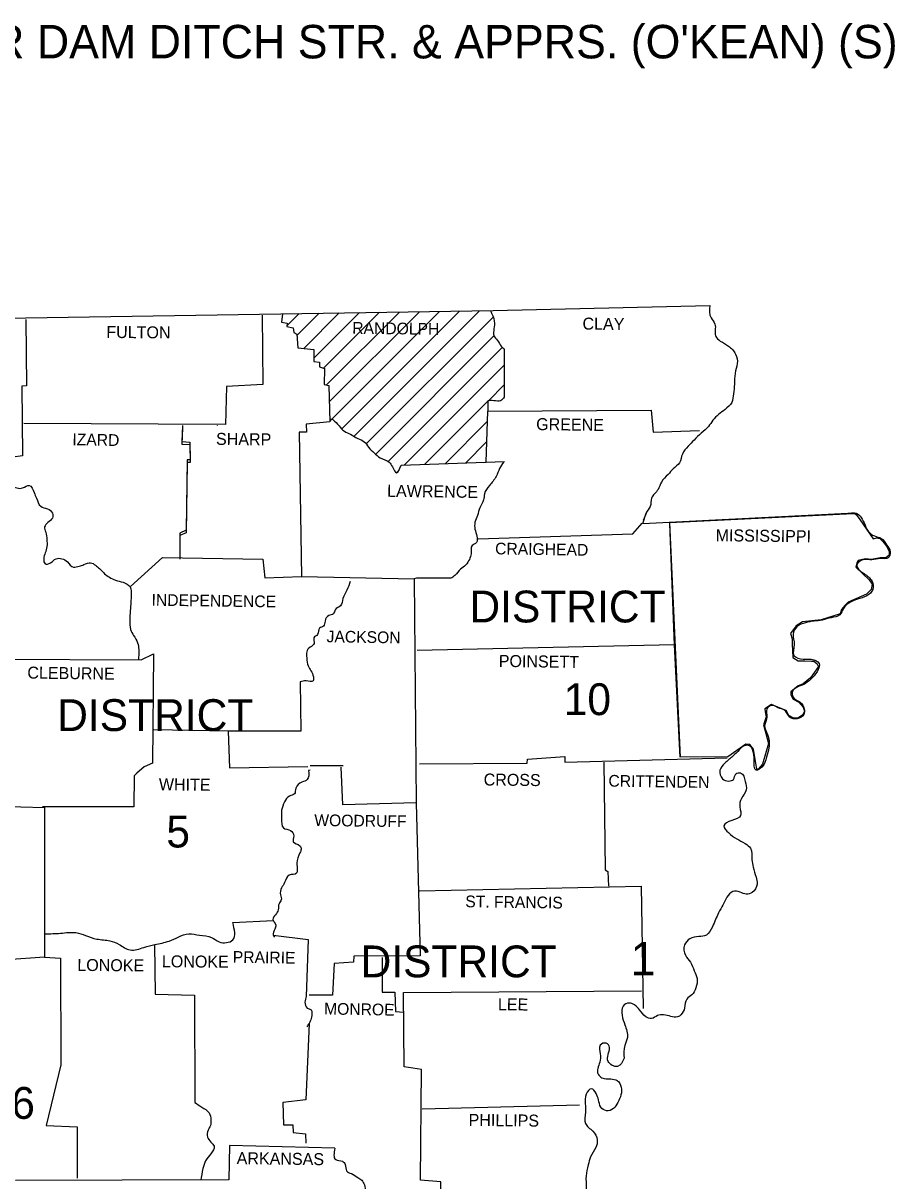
# Model space of a CAD drawing. Extents: x 166 to 3406, y 71 to 2074.
# Drawn here: x 2979.2 to 3284.8, y 1629.3 to 2035 of the extents above; entities that cross this region are included whole.
import ezdxf

# ---------------------------------------------------------------- set-up
doc = ezdxf.new("R2010")
doc.units = 0
for name, color, linetype in [('1', 7, 'Continuous'), ('2', 7, 'Continuous'), ('3', 7, 'Continuous'), ('R_Border', 7, 'Continuous'), ('S_MISC_BOUNDARY', 7, 'Continuous')]:
    doc.layers.add(name, color=color, linetype=linetype)

msp = doc.modelspace()

# ---------------------------------------------------------------- linework, layer by layer
at = {"layer": '1'}
for p, q in [((3071.63, 1928.88), (3075.94, 1933.18)), ((3075.16, 1925.49), (3082.96, 1933.29)), ((3077.59, 1921), (3089.99, 1933.4)), ((3081.01, 1917.5), (3097.02, 1933.51)), ((3084.5, 1914.07), (3104.05, 1933.62)), ((3085.51, 1908.16), (3111.08, 1933.73)), ((3086.47, 1902.21), (3118.1, 1933.84)), ((3086.67, 1895.49), (3125.13, 1933.95)), ((3090.89, 1892.79), (3132.16, 1934.06)), ((3095.19, 1890.17), (3139.19, 1934.17)), ((3099.42, 1887.48), (3144.12, 1932.19)), ((3102.75, 1883.89), (3144.23, 1925.37)), ((3107.2, 1881.43), (3147.11, 1921.33)), ((3112.76, 1880.07), (3147.77, 1915.08)), ((3142.25, 1902.63), (3147.81, 1908.2)), ((3119.91, 1880.3), (3142.06, 1902.45)), ((3127.07, 1880.54), (3141.96, 1895.43)), ((3134.22, 1880.77), (3141.75, 1888.31)), ((3141.37, 1881), (3141.55, 1881.18)), ((3110.08, 1877.38), (3111.01, 1878.32)), ((3196.36, 1859.58), (3197.54, 1863.21)), ((3196.66, 1860.76), (3197.83, 1863.6)), ((3079.74, 1774.85), (3091.38, 1774.85))]:
    msp.add_line(p, q, dxfattribs=at)
for points in [[(2683.09, 1931.5), (2841.3, 1931.4), (2980.13, 1931.69), (3143.92, 1934.24), (3219.84, 1936)], [(2980.13, 1931.11), (2980.33, 1907.82), (2978.67, 1907.72), (2978.96, 1883.36), (2972.11, 1882.38), (2972.7, 1875.83), (2975.05, 1872.79), (2974.85, 1865.06), (2961.54, 1864.57), (2961.06, 1852.64), (2948.92, 1852.25), (2948.34, 1837.77), (2949.02, 1836.59), (2949.31, 1813.5), (2970.25, 1812.13), (2969.96, 1760.57), (2986.59, 1760.08), (2986.59, 1707.64), (2973.48, 1706.66), (2972.5, 1695.11), (2950.49, 1695.02)], [(3063.01, 1932.57), (3063.2, 1908.31), (3050.48, 1907.62), (3050.09, 1894.32), (2979.35, 1894.71)], [(3070.13, 1933.09), (3069.76, 1930.13), (3071.71, 1929.83), (3071.62, 1928.66), (3073.87, 1928.17), (3074.06, 1926.61), (3075.14, 1925.92), (3075.43, 1921.22), (3081.01, 1920.64), (3081.01, 1916.43), (3083.06, 1916.14), (3083.06, 1914.47), (3084.82, 1913.98), (3084.73, 1908.31), (3086.29, 1908.02), (3086.68, 1895.2), (3078.37, 1894.42), (3078.46, 1891.68), (3075.92, 1891.58), (3076.8, 1841.09), (3116.23, 1840.21), (3116.92, 1761.74), (3091.18, 1761.06), (3090.69, 1774.27)], [(3147.74, 1920.83), (3147.83, 1903.91)], [(3141.54, 1881.08), (3142.06, 1899.01), (3142.06, 1899.01), (3199.3, 1899.31), (3200.08, 1891.68), (3216.22, 1892.26)], [(3035.02, 1894.02), (3034.83, 1888.35), (3037.57, 1888.15), (3037.66, 1881.89), (3036.69, 1881.89), (3036.29, 1857.24), (3034.04, 1856.26), (3034.04, 1848.04)], [(3035.02, 1893.14), (3034.83, 1887.47), (3037.57, 1887.27), (3037.66, 1881.01), (3036.69, 1881.01), (3036.29, 1856.36), (3034.04, 1855.38), (3034.04, 1847.16)], [(3047.25, 1893.83), (3047.35, 1893.93)], [(3111.63, 1880.03), (3147.93, 1881.31)], [(3196.36, 1859.58), (3270.62, 1863.4)], [(3138.64, 1854.2), (3192.94, 1855.96), (3196.17, 1859.68)], [(3205.75, 1859.49), (3207.42, 1817.12), (3209.37, 1777.69)], [(3016.82, 1837.57), (3027.98, 1847.65), (3063.2, 1847.16), (3063.89, 1840.6), (3076.7, 1841.09)], [(3129.05, 1840.41), (3117.11, 1840.41), (3116.23, 1840.21)], [(2970.25, 1812.13), (3020.54, 1811.84), (3024.85, 1813.89), (3024.55, 1775.64), (3021.62, 1774.37), (3018.98, 1772.12), (3018.1, 1771.23), (3018, 1760.28), (2986, 1760.28)], [(3207.42, 1817.12), (3117.31, 1815.07)], [(3076.31, 1804.11), (3076.51, 1786.89), (3051.07, 1786.79), (3024.95, 1787.28)], [(3051.07, 1786.79), (3051.46, 1773.97), (3078.95, 1774.46)], [(3118.09, 1775.44), (3155.86, 1775.64), (3155.95, 1777.01), (3169.06, 1777.99), (3169.06, 1775.93), (3226.01, 1777.5)], [(3079.74, 1773.19), (3079.25, 1773.09)], [(3182.76, 1775.93), (3183.25, 1738.26), (3184.13, 1737.68), (3184.43, 1732.59)], [(3116.92, 1761.74), (3118.38, 1708.13), (3095.1, 1708.03), (3095, 1705.88), (3088.25, 1705.49), (3087.66, 1694.33), (3079.44, 1694.33)], [(3118.09, 1730.92), (3195.78, 1732.49)], [(3195.78, 1732.49), (3196.56, 1689.64)], [(3052.63, 1719.77), (3066.82, 1720.46)], [(3025.24, 1712.14), (3025.43, 1694.63), (3039.23, 1694.33), (3039.33, 1656.76)], [(3066.82, 1715.37), (3079.05, 1713.8), (3078.37, 1693.84)], [(2986.59, 1707.64), (2992.27, 1707.25), (2992.36, 1669.87), (2987.28, 1648.64), (2998.14, 1648.15), (2998.04, 1630.15)], [(3105.08, 1707.54), (3104.98, 1695.41), (3109.48, 1695.41), (3109.68, 1688.66), (3112.51, 1688.36)], [(3118.09, 1608.62), (3125.72, 1609.11), (3125.62, 1628.97), (3118.48, 1629.46), (3118.87, 1668.31), (3112.71, 1669.19), (3112.51, 1695.31), (3195.97, 1695.9)], [(3079.44, 1684.45), (3078.27, 1657.64), (3070.25, 1656.76), (3070.44, 1648.84), (3073.67, 1648.93), (3073.77, 1646.19), (3078.17, 1645.71), (3078.27, 1642.48)], [(3119.07, 1654.51), (3174.25, 1655.88)], [(3088.44, 1640.72), (3051.46, 1641.69), (3051.26, 1629.66), (2976.42, 1629.37)]]:
    msp.add_lwpolyline(points, dxfattribs=at)
for points in [[(3219.84, 1936), (3220.33, 1931.69), (3221.7, 1929.44), (3221.9, 1925.33), (3223.56, 1923.57), (3226.4, 1921.81), (3228.94, 1918.97), (3229.53, 1915.65), (3228.75, 1912.22), (3228.55, 1908.41), (3228.16, 1905.08), (3227.57, 1902.05), (3225.23, 1899.6), (3222.97, 1897.84), (3220.92, 1895.79), (3219.45, 1893.63), (3216.91, 1891.29), (3214.36, 1888.84), (3212.31, 1886.69), (3210.26, 1883.95), (3209.28, 1880.91), (3207.03, 1878.76), (3205.27, 1876.8), (3202.92, 1874.16), (3201.74, 1871.52), (3199.49, 1868.49), (3199, 1865.55), (3197.54, 1863.21), (3197.44, 1862.81)], [(3142.98, 1934.23), (3144.31, 1930.52), (3144.21, 1927.88), (3144.21, 1925.43), (3145.48, 1923.77), (3146.76, 1921.71), (3147.74, 1920.83)], [(3147.83, 1903.91), (3146.56, 1902.63), (3144.12, 1902.63), (3142.06, 1902.63)], [(3087.76, 1896.08), (3089.91, 1893.83), (3091.77, 1891.97), (3093.92, 1890.89), (3096.47, 1889.43), (3098.72, 1888.25), (3100.18, 1886.39), (3102.24, 1884.34), (3104.29, 1882.68), (3107.52, 1881.11), (3108.6, 1879.45), (3110.07, 1877.39), (3111.63, 1880.03)], [(3147.64, 1881.21), (3146.17, 1878.86), (3145, 1876.12), (3142.65, 1872.99), (3140.89, 1869.96), (3140.59, 1867.9), (3139.22, 1865.16), (3138.44, 1862.42), (3137.56, 1860.07), (3137.56, 1857.63), (3138.24, 1855.18), (3138.05, 1852.93), (3136.58, 1851.86), (3136.19, 1849.02), (3135.6, 1847.06), (3134.33, 1845.1), (3132.47, 1843.64), (3130.52, 1841.39), (3129.05, 1840.41)], [(2975.05, 1872.79), (2978.96, 1872.11), (2981.31, 1872.99), (2982.97, 1870.45), (2983.85, 1868.49), (2985.32, 1865.65), (2987.67, 1864.77), (2989.43, 1863.21), (2989.43, 1861.54), (2987.86, 1859.98), (2986.69, 1858.41), (2987.08, 1856.55), (2987.47, 1854.01), (2987.47, 1851.56), (2986.89, 1849.31), (2986.4, 1847.26), (2986.89, 1845.5), (2988.74, 1845.79), (2990.7, 1847.26), (2992.76, 1847.26), (2994.71, 1846.18), (2996.77, 1844.32), (2998.82, 1844.71), (3000.49, 1845.2), (3002.83, 1845.89), (3004.5, 1845.01), (3005.96, 1843.83), (3007.73, 1841.97), (3009.39, 1840.8), (3011.54, 1839.72), (3014.18, 1839.04), (3016.63, 1837.38), (3017.02, 1834.54), (3016.92, 1832.09), (3016.73, 1829.06), (3016.53, 1825.73), (3016.82, 1822.5), (3017.9, 1820.35), (3019.27, 1817.81), (3019.66, 1815.46), (3019.56, 1811.74)], [(3269.55, 1863.3), (3270.62, 1863.4), (3273.95, 1859.88), (3275.42, 1856.94), (3277.57, 1855.28), (3280.02, 1854.4), (3281.87, 1852.15), (3283.15, 1849.7), (3282.46, 1847.55), (3279.72, 1847.35), (3276.69, 1846.87), (3273.75, 1846.96), (3271.41, 1845.01), (3273.56, 1842.36), (3276.4, 1839.92), (3277.18, 1837.28), (3275.61, 1834.73), (3272.48, 1833.36), (3269.45, 1832.19), (3266.71, 1829.84), (3265.44, 1827.59), (3262.4, 1826.61), (3259.27, 1825.73), (3256.53, 1825.44), (3253.4, 1824.85), (3250.37, 1823.38), (3249.1, 1820.84), (3249.49, 1817.22), (3249.39, 1813.4), (3252.62, 1812.13), (3255.46, 1812.03), (3258.2, 1810.57), (3257.9, 1808.41), (3255.85, 1805.67), (3253.4, 1803.52), (3250.96, 1802.45), (3248.71, 1800.39), (3249.49, 1798.34), (3251.54, 1796.97), (3253.01, 1794.72), (3252.82, 1792.66), (3250.47, 1791.19), (3247.92, 1791.78), (3246.07, 1794.23), (3243.91, 1795.01), (3242.05, 1795.89), (3239.9, 1794.62), (3239.9, 1791.78), (3239.12, 1788.75), (3239.8, 1786.5), (3240.68, 1783.37), (3240.59, 1781.02), (3239.8, 1777.69), (3238.14, 1774.27), (3236.18, 1773.19), (3235.4, 1776.91), (3235.01, 1779.94), (3233.84, 1781.7), (3232.27, 1781.8), (3230.22, 1780.33), (3227.96, 1778.08), (3225.13, 1775.64), (3223.46, 1773.19), (3224.34, 1770.16), (3226.5, 1769.38), (3228.16, 1769.96), (3229.04, 1771.92), (3230.7, 1772.21), (3232.27, 1769.18)], [(3093.83, 1839.33), (3092.65, 1836.3), (3091.28, 1833.36), (3090.4, 1830.82), (3088.54, 1829.35), (3087.95, 1827.98), (3086.29, 1827.4), (3085.02, 1825.44), (3084.43, 1823.68), (3083.06, 1822.89), (3082.38, 1820.74), (3081.11, 1819.57), (3081.2, 1817.61), (3079.74, 1816.24), (3078.56, 1814.68), (3078.56, 1812.52), (3079.05, 1809.69), (3080.03, 1808.02), (3080.91, 1805.87), (3080.81, 1804.5), (3078.37, 1804.5), (3076.31, 1804.11)], [(3079.25, 1773.09), (3078.76, 1769.87), (3076.9, 1768.98), (3074.75, 1766.83), (3074.26, 1764.88), (3072.5, 1764.09), (3070.83, 1762.04), (3069.76, 1759.2), (3069.76, 1756.27), (3070.44, 1752.94), (3072.89, 1752.06), (3074.06, 1750.1), (3073.87, 1748.05), (3076.21, 1746.68), (3076.61, 1745.5), (3076.21, 1744.23), (3075.14, 1740.61), (3075.24, 1738.16), (3075.04, 1737.09), (3072.4, 1736.4), (3070.83, 1733.76), (3069.76, 1731.9), (3069.36, 1729.46), (3069.66, 1727.7), (3068.88, 1726.33), (3068.58, 1724.27), (3067.6, 1722.51), (3066.72, 1720.85), (3067.7, 1718.89), (3067.41, 1717.52), (3066.82, 1715.37), (3067.31, 1714.68)], [(3232.27, 1769.18), (3232.66, 1766.34), (3231, 1763.31), (3230.41, 1760.28), (3230.7, 1757.24), (3227.57, 1755.58), (3224.83, 1753.62), (3226.4, 1751.28), (3229.33, 1749.12), (3232.27, 1747.46), (3234.13, 1745.8), (3234.62, 1741.78), (3235.11, 1739.24), (3236.09, 1735.72), (3236.48, 1733.27), (3234.72, 1730.34), (3232.66, 1729.75), (3230.51, 1730.44), (3227.96, 1730.63), (3225.91, 1728.67), (3224.44, 1725.93), (3222.97, 1723.2), (3221.9, 1720.85), (3220.82, 1718.3), (3218.67, 1715.37), (3216.03, 1714.88), (3212.9, 1714.1), (3211.04, 1711.94), (3211.33, 1708.32), (3213.09, 1705.88), (3214.46, 1702.84), (3215.44, 1700.2), (3214.95, 1696.88), (3213.58, 1694.43), (3211.82, 1692.96), (3211.04, 1689.83), (3209.77, 1687.48), (3208.59, 1686.7), (3206.24, 1686.9), (3203.7, 1687.39), (3201.55, 1687.19), (3199.49, 1686.11), (3197.44, 1686.8), (3195.29, 1689.15), (3193.52, 1690.91), (3191.57, 1691.59), (3189.51, 1690.52), (3189.12, 1687.29), (3190.1, 1683.96), (3190.98, 1679.46), (3190.1, 1676.72), (3189.81, 1672.22)], [(2986.79, 1715.86), (2992.27, 1716.05), (2997.65, 1716.25), (3001.07, 1715.27), (3004.99, 1714), (3009.58, 1713.41), (3012.81, 1712.14), (3016.63, 1710.18), (3021.52, 1711.06), (3025.34, 1712.04), (3030.33, 1713.31), (3033.56, 1714.68), (3037.27, 1715.86), (3040.99, 1715.37), (3045.2, 1714.59), (3047.84, 1713.02), (3052.63, 1713.7), (3052.63, 1719.77)], [(3078.37, 1693.84), (3077.97, 1691.89), (3078.76, 1689.83), (3080.13, 1689.15), (3080.32, 1687.19), (3079.83, 1685.23), (3079.44, 1684.45), (3078.56, 1683.28)], [(3189.81, 1672.22), (3187.56, 1669.38), (3184.23, 1671.14), (3184.23, 1673.49), (3184.72, 1675.94), (3183.55, 1677.5), (3181.49, 1676.82), (3181.49, 1673.79), (3181.29, 1670.85), (3180.71, 1666.64), (3182.08, 1665.37), (3185.21, 1664.98), (3187.46, 1664.39), (3188.83, 1662.14), (3188.73, 1659.4), (3187.65, 1656.76), (3186.09, 1654.61), (3183.64, 1653.83), (3181.69, 1655.1), (3180.9, 1657.64), (3180.02, 1659.89), (3178.36, 1661.56), (3176.6, 1659.7), (3176.21, 1656.27), (3176.3, 1653.34), (3176.3, 1649.33), (3178.85, 1646.68), (3180.41, 1643.65), (3179.92, 1640.91), (3178.07, 1637.68), (3177.28, 1634.84), (3176.5, 1631.03), (3176.6, 1626.82), (3175.91, 1622.71), (3174.54, 1619.97), (3172, 1617.72), (3170.34, 1616.26), (3168.97, 1614.79), (3168.28, 1611.85), (3167.79, 1609.8), (3165.93, 1607.35), (3164.47, 1607.16), (3163.29, 1608.13), (3162.9, 1609.8), (3162.9, 1611.46), (3162.12, 1613.12), (3159.67, 1613.81), (3157.72, 1613.71), (3156.83, 1612.34), (3158.11, 1608.53), (3158.6, 1606.08), (3157.91, 1602.75), (3158.3, 1602.36), (3154.78, 1600.5), (3151.94, 1600.21), (3149.59, 1599.52), (3147.34, 1598.06), (3146.27, 1595.9), (3144.7, 1594.14), (3143.33, 1592.48), (3141.47, 1591.7), (3139.42, 1592.09), (3136.68, 1592.38), (3135.11, 1590.43), (3135.6, 1587.59), (3137.46, 1585.92), (3140.2, 1585.14), (3143.04, 1585.34), (3145.78, 1585.63), (3148.32, 1584.26), (3147.83, 1581.62), (3145.39, 1580.35), (3141.77, 1579.96), (3138.83, 1580.25), (3135.31, 1579.47), (3133.55, 1577.22), (3134.53, 1573.79), (3138.34, 1572.42), (3140.1, 1569.19), (3140.2, 1566.16), (3138.93, 1562.15), (3137.17, 1560.29), (3133.74, 1559.51), (3131.1, 1559.02), (3130.71, 1554.52), (3129.54, 1552.27), (3127.48, 1551.58), (3124.55, 1553.05), (3122.79, 1553.73), (3120.63, 1554.71), (3117.89, 1556.38), (3115.84, 1556.08), (3116.43, 1551.78), (3116.62, 1551.58), (3118.97, 1548.35), (3121.32, 1545.81), (3122.39, 1542.78)], [(3039.33, 1656.76), (3041.77, 1655.1), (3044.32, 1653.14), (3045, 1650.5), (3044.81, 1648.64), (3044.02, 1647.07), (3043.83, 1644.63), (3045, 1642.87), (3046.08, 1641.4), (3045, 1638.76), (3043.14, 1636.31), (3042.17, 1633.57), (3041.48, 1629.46)], [(3088.44, 1640.72), (3088.74, 1636.7), (3091.09, 1636.12), (3092.06, 1635.04), (3092.55, 1632.79), (3094.22, 1631.81), (3096.47, 1630.44), (3097.84, 1629.46), (3098.81, 1627.9), (3099.4, 1625.35), (3100.97, 1623.69), (3103.12, 1622.91), (3104.69, 1621.05), (3105.66, 1618.41), (3107.23, 1617.23), (3108.79, 1615.18), (3109.58, 1614.3), (3110.95, 1611.95), (3112.32, 1610.78), (3113.3, 1610.09), (3114.86, 1609.6), (3116.82, 1608.33), (3118.09, 1606.37), (3118.09, 1604.91), (3117.6, 1602.66), (3117.21, 1600.31), (3117.01, 1597.67), (3116.82, 1595.32), (3117.7, 1593.36), (3117.21, 1590.43), (3116.23, 1588.86), (3116.13, 1586.71), (3115.84, 1583.48), (3115.45, 1581.62), (3114.57, 1578.59), (3113.3, 1577.02)]]:
    msp.add_spline(points, degree=3, dxfattribs=at)
at = {"layer": 'S_MISC_BOUNDARY'}
for p, q in [((3142.06, 1902.63), (3142.06, 1899.01)), ((3087.76, 1896.08), (3086.66, 1896.05)), ((3205.83, 1859.94), (3270.2, 1863.11)), ((3270.2, 1863.11), (3270.75, 1863.14)), ((3270.75, 1863.14), (3271.2, 1862.82)), ((3271.2, 1862.82), (3272.45, 1861.03)), ((3209.65, 1777.68), (3205.83, 1859.94)), ((3272.45, 1861.03), (3274.79, 1857.65)), ((3274.79, 1857.65), (3277.14, 1854.27)), ((3277.14, 1854.27), (3278.32, 1854.59)), ((3278.32, 1854.59), (3279.51, 1854.39)), ((3279.51, 1854.39), (3280.6, 1853.28)), ((3280.6, 1853.28), (3281.82, 1851.65)), ((3281.82, 1851.65), (3282.75, 1849.85)), ((3271.52, 1846.1), (3271.06, 1844.3)), ((3271.93, 1846.65), (3271.52, 1846.1)), ((3274.44, 1847.2), (3271.93, 1846.65)), ((3276.52, 1846.96), (3274.44, 1847.2)), ((3279.66, 1847.59), (3276.52, 1846.96)), ((3281.55, 1847.61), (3279.66, 1847.59)), ((3282.76, 1848.47), (3281.55, 1847.61)), ((3282.75, 1849.85), (3282.76, 1848.47)), ((3271.06, 1844.3), (3275.77, 1839.93)), ((3275.77, 1839.93), (3276.84, 1838.33)), ((3276.84, 1838.33), (3276.42, 1836.44)), ((3274.82, 1834.83), (3268.44, 1832)), ((3276.42, 1836.44), (3274.82, 1834.83)), ((3267.18, 1830.93), (3266.04, 1829.44)), ((3268.44, 1832), (3267.18, 1830.93)), ((3258.9, 1825.91), (3252.33, 1825.21)), ((3265.54, 1828.01), (3258.9, 1825.91)), ((3266.04, 1829.44), (3265.54, 1828.01)), ((3250.11, 1823.8), (3248.15, 1821.04)), ((3252.33, 1825.21), (3250.11, 1823.8)), ((3248.15, 1821.04), (3248.76, 1819.25)), ((3248.76, 1819.25), (3248.76, 1817.37)), ((3248.76, 1817.37), (3248.94, 1812.7)), ((3248.94, 1812.7), (3250.91, 1811.52)), ((3250.91, 1811.52), (3253.2, 1811.45)), ((3253.2, 1811.45), (3255.49, 1811.38)), ((3258.05, 1809.49), (3255.24, 1805.49)), ((3255.49, 1811.38), (3256.33, 1811.35)), ((3256.33, 1811.35), (3257.4, 1810.55)), ((3257.4, 1810.55), (3258.05, 1809.49)), ((3255.24, 1805.49), (3252.61, 1803.49)), ((3250.88, 1802.76), (3248.25, 1800.63)), ((3252.61, 1803.49), (3250.88, 1802.76)), ((3248.25, 1800.63), (3248.34, 1799.63)), ((3248.34, 1799.63), (3249.15, 1798.1)), ((3249.15, 1798.1), (3251.08, 1797.04)), ((3241.55, 1796.22), (3239.23, 1794.72)), ((3239.23, 1794.72), (3239.34, 1793.59)), ((3239.34, 1793.59), (3239.68, 1791.91)), ((3243.78, 1795.31), (3241.55, 1796.22)), ((3246.67, 1794.12), (3243.78, 1795.31)), ((3247.63, 1792.37), (3246.67, 1794.12)), ((3251.08, 1797.04), (3252.56, 1795.24)), ((3253.07, 1793.83), (3252.5, 1792.58)), ((3252.56, 1795.24), (3253.07, 1793.83)), ((3239.68, 1791.91), (3238.7, 1789.08)), ((3249.36, 1791.39), (3247.63, 1792.37)), ((3250.76, 1791.45), (3249.36, 1791.39)), ((3252.5, 1792.58), (3250.76, 1791.45)), ((3238.7, 1789.08), (3240.43, 1782.58)), ((3232.48, 1782.27), (3226.19, 1777.8)), ((3233.89, 1782.17), (3232.48, 1782.27)), ((3235.17, 1780.59), (3233.89, 1782.17)), ((3240.43, 1782.58), (3238.38, 1775.26)), ((3226.19, 1777.8), (3209.65, 1777.68)), ((3236.39, 1773.48), (3235.17, 1780.59)), ((3236.94, 1773.68), (3236.39, 1773.48)), ((3238.38, 1775.26), (3236.94, 1773.68))]:
    msp.add_line(p, q, dxfattribs=at)

# ---------------------------------------------------------------- texts
at = {"layer": '1'}
msp.add_text('1', height=11.74, dxfattribs=at).set_placement((3192.16, 1701.28))
at = {"layer": '2'}
for s, height, rotation, p in [('CLAY', 4.206, 359.2258, (3175.23, 1927.58)), ('FULTON', 4.206, 359.4996, (3008.31, 1924.65)), ('RANDOLPH', 4.109, 359.2583, (3094.51, 1926.12)), ('GREENE', 4.207, 359.2361, (3158.99, 1892.36)), ('IZARD', 4.108, 358.9258, (2996.38, 1887.08)), ('SHARP', 4.206, 359.3905, (3046.76, 1887.18)), ('LAWRENCE', 4.207, 359.2678, (3106.74, 1868.98)), ('MISSISSIPPI', 4.2062, 359.3097, (3221.9, 1853.42)), ('CRAIGHEAD', 4.109, 359.1159, (3144.6, 1848.82)), ('INDEPENDENCE', 4.1081, 359.2187, (3024.16, 1830.82)), ('JACKSON', 4.108, 359.1352, (3085.51, 1818)), ('POINSETT', 4.206, 359.1987, (3145.88, 1809.39)), ('CLEBURNE', 4.206, 359.2535, (2980.62, 1805.28)), ('WHITE', 4.207, 359.3139, (3026.71, 1766.15)), ('CROSS', 4.206, 359.3839, (3140.59, 1767.81)), ('CRITTENDEN', 4.109, 359.213, (3184.33, 1767.42)), ('WOODRUFF', 4.108, 359.2748, (3081.2, 1753.62)), ('ST. FRANCIS', 4.1081, 359.2216, (3134.14, 1725.15)), ('LONOKE', 4.207, 359.4974, (3027.78, 1704.12)), ('PRAIRIE', 4.109, 359.2116, (3052.63, 1705.68)), ('LONOKE', 4.207, 359.4974, (2998.14, 1702.84)), ('LEE', 4.207, 359.4327, (3145.58, 1689.05)), ('MONROE', 4.108, 359.0331, (3084.63, 1687.58)), ('PHILLIPS', 4.206, 359.3179, (3135.31, 1648.54)), ('ARKANSAS', 4.206, 359.2678, (3054, 1635.14))]:
    msp.add_text(s, height=height, rotation=rotation, dxfattribs=at).set_placement(p)
at = {"layer": '3'}
for s, height, p in [('DISTRICT', 11.154, (3135.6, 1824.95)), ('10', 11.154, (3168.67, 1792.47)), ('DISTRICT', 11.154, (2991.09, 1786.89)), ('5', 11.15, (3029.35, 1746.09)), ('DISTRICT', 11.154, (3097.45, 1700.59)), ('DISTRICT 6', 11.154, (2902.06, 1650.99))]:
    msp.add_text(s, height=height, dxfattribs=at).set_placement(p)
at = {"layer": 'R_Border'}
msp.add_text("BEAVER DAM DITCH STR. & APPRS. (O'KEAN) (S)", height=11.724, dxfattribs=at).set_placement((2916.01, 2022.61))

doc.saveas('drawing.dxf')
